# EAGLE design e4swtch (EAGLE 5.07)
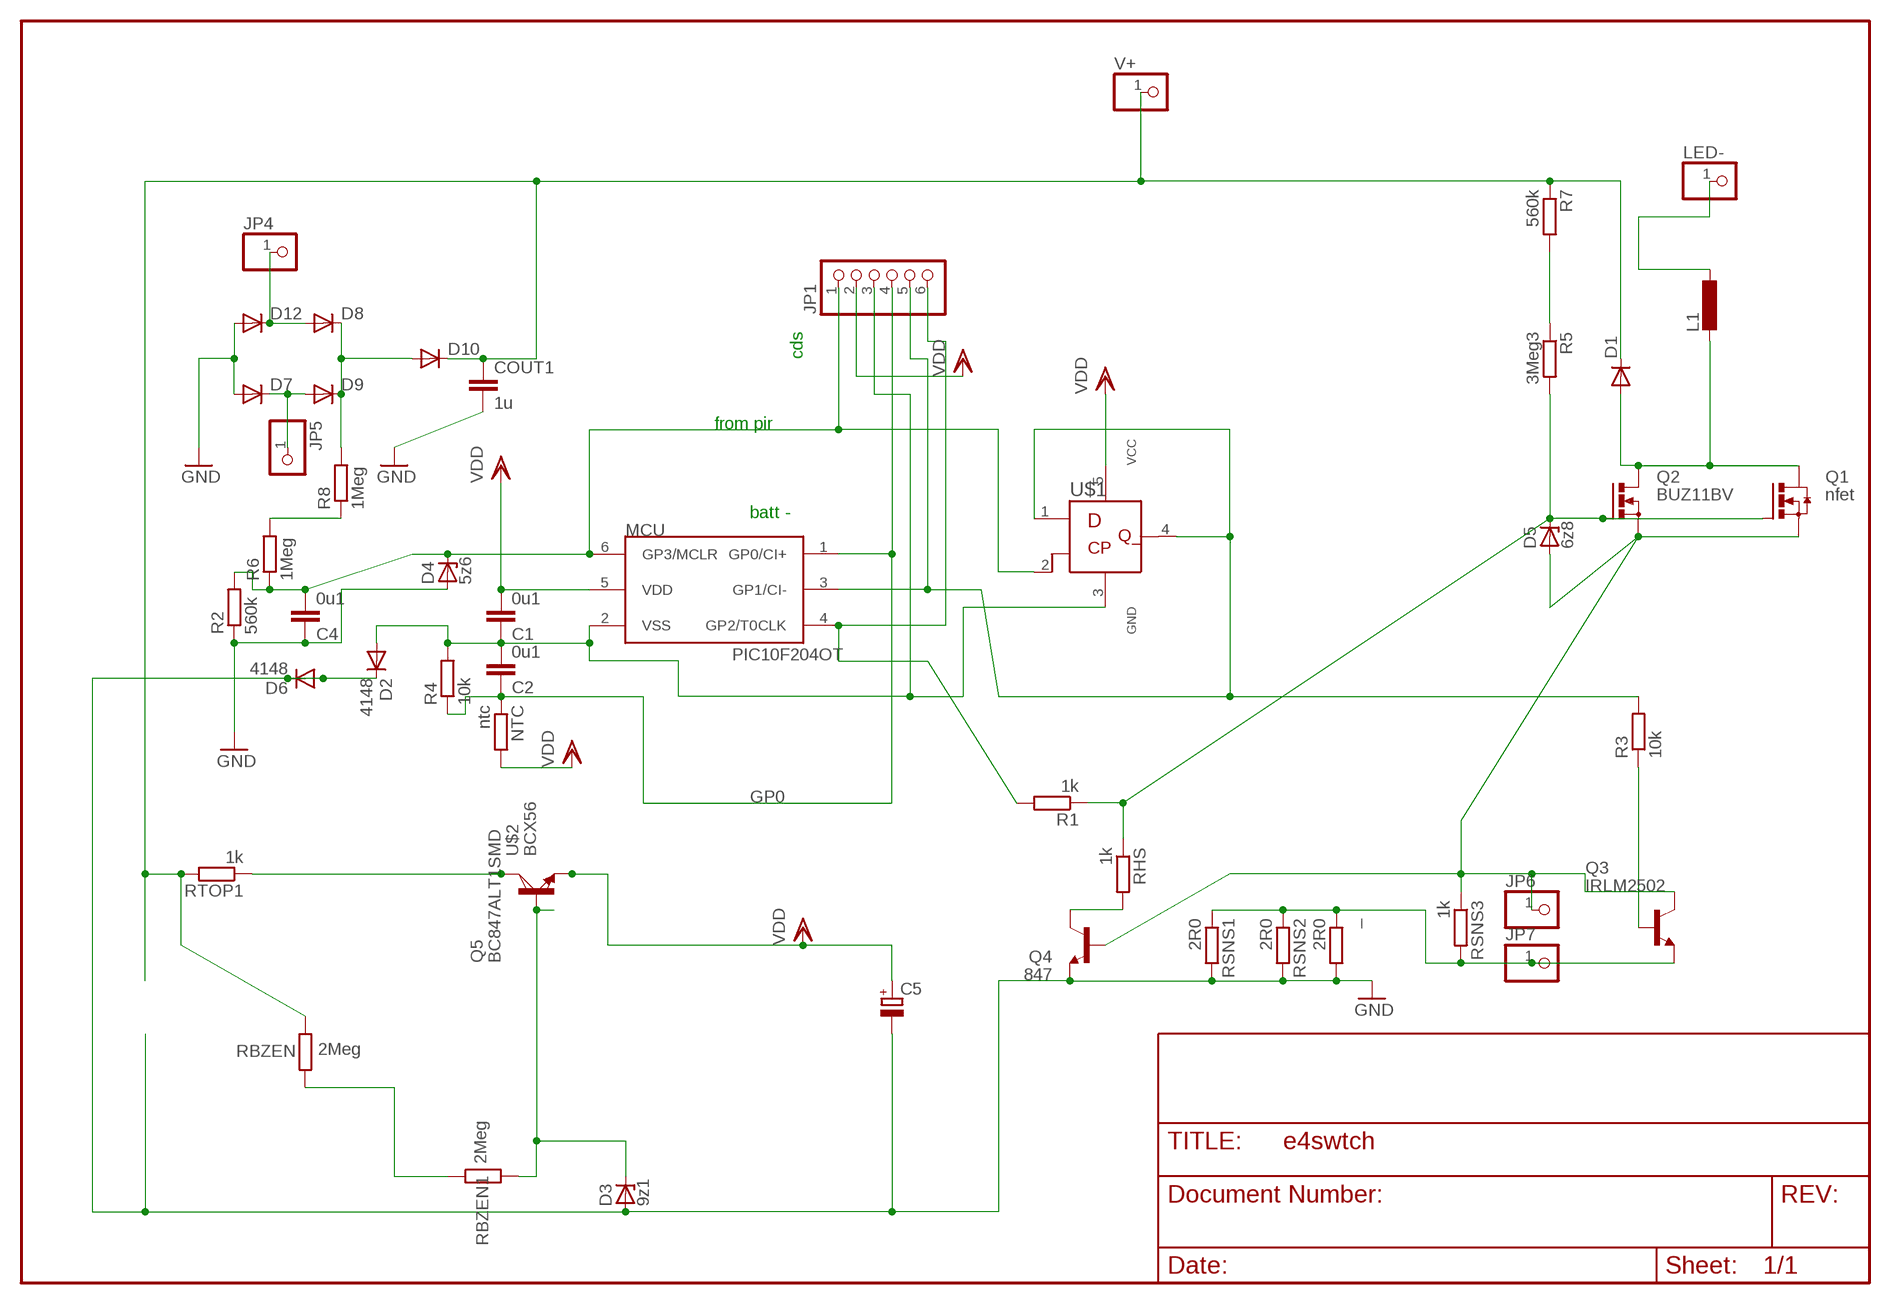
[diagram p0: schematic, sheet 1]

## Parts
_  2R0  R-EU_R2010  [R2010]
C1  0u1  C-EUC0805  [C0805]
C2  0u1  C-EUC0805  [C0805]
C4  0u1  C-EUC1206  [C1206]
C5  CPOL-EUSANYO_SMD_B6  [SANYO-OSCON_SMD_B6]
COUT1  1u  C-EU075-032X103  [C075-032X103]
D1  DIODE-SMC  [SMC]
D2  4148  1N4148MINIMELF  [MINIMELF]
D3  9z1  ZENER-DIODESOD80C  [SOD80C]
D4  5z6  ZENER-DIODESOD80C  [SOD80C]
D5  6z8  ZENER-DIODESOD80C  [SOD80C]
D6  4148  1N4148MINIMELF  [MINIMELF]
D7  DIODE-SMA-DO214  [SMA-DO214AC]
D8  DIODE-SMA-DO214  [SMA-DO214AC]
D9  DIODE-SMA-DO214  [SMA-DO214AC]
D10  DIODE-SMA-DO214  [SMA-DO214AC]
D12  DIODE-SMA-DO214  [SMA-DO214AC]
JP1  PINHD-1X6  [1X06BOX]
JP4  PINHD-1X11MM6  [1X1MM8]
JP5  PINHD-1X11MM6  [1X1MM8]
JP6  PINHD-1X1INCH  [1X01]
JP7  PINHD-1X1INCH  [1X01]
L1  L-EUPIS2816  [PIS2816]
LED-  PINHD-1X11MM6  [1X1MM8]
MCU  PIC10F204OT  [SOT23-6]
NTC  ntc  R-EU_0204/5  [0204/5]
Q1  nfet  N-HEXFET_DPAK-  [TO252]
Q2  BUZ11BV  [TO220BV]
Q3  IRLM2502  BC847ALT1SMD  [SOT23]
Q4  847  BC847ASMD  [SOT23]
Q5  BC847ALT1SMD  [SOT23]
R1  1k  R-EU_R0805  [R0805]
R2  560k  R-EU_R0805  [R0805]
R3  10k  R-EU_R0805  [R0805]
R4  10k  R-EU_R0805  [R0805]
R5  3Meg3  R-EU_R1206  [R1206]
R6  1Meg  R-EU_R1206  [R1206]
R7  560k  R-EU_R1206  [R1206]
R8  1Meg  R-EU_R1206  [R1206]
RBZEN  2Meg  R-EU_R1206  [R1206]
RBZEN1  2Meg  R-EU_R1206  [R1206]
RHS  1k  R-EU_0204/5  [0204/5]
RSNS1  2R0  R-EU_R2512  [R2512]
RSNS2  2R0  R-EU_R1206  [R1206]
RSNS3  1k  R-EU_R1206  [R1206]
RTOP1  1k  R-EU_R1206  [R1206]
U$1  7479SOT23  [SOT23-5]
U$2  BCX56  [SOT223]
V+  PINHD-1X11MM6  [1X1MM8]

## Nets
AC1: D8.A D12.K(C) JP4.1
AC2: D7.K(C) D9.A JP5.1
BSW1: _.1 JP7.1 Q3.2(E) RSNS1.1 RSNS2.1 RSNS3.2
C: Q5.3(C) RTOP1.1 U$2.2(C)
CB: D3.C Q5.1(B) RBZEN1.2 U$2.1(B)
GND: _.2 C4.1 C5.- COUT1.2 D2.C D3.A D4.A D6.A D6.C D7.A D12.A Q4.2(E) R2.1 RSNS1.2 RSNS2.2
GP0: C2.1 JP1.4 MCU.1(GP0/CI+) NTC.1 R4.1
HOT: D1.A L1.2 Q1.3(D) Q2.D
LED-: L1.1 LED-.1
N$1: D5.C Q1.1(G) Q2.G R1.1 R5.2 RHS.1
N$2: JP1.5 MCU.3(GP1/CI-) R3.2 U$1.1(D) U$1.4(Q_)
N$3: C4.2 D4.C JP1.1 MCU.6(GP3/MCLR) R2.2 R6.1 U$1.2(CP)
N$4: R5.1 R7.2
N$5: Q3.1(B) R3.1
N$6: RBZEN1.1 RBZEN.2
N$7: Q4.3(C) RHS.2
N$9: R6.2 R8.1
N$14: JP1.6 MCU.4(GP2/T0CLK) R1.2
N$16: D8.K(C) D9.K(C) D10.A R8.2
S: D5.A JP6.1 Q1.2(S) Q2.S Q3.3(C) Q4.1(B) RSNS3.1
VDD: C1.2 C5.+ JP1.2 MCU.5(VDD) NTC.2 Q5.2(E) U$1.5(VCC) U$2.3(E)
VPLUS: COUT1.1 D1.C D10.K(C) R7.1 RBZEN.1 RTOP1.2 V+.1
VSS: C1.1 C2.2 D2.A JP1.3 MCU.2(VSS) R4.2 U$1.3(GND)

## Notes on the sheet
- cds
- from pir
- batt -

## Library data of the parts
_ NTC R1 R3 R5 R7 RBZEN RBZEN1 RHS RSNS1-RSNS3 RTOP1 = rcl:R-EU_: RESISTOR, European symbol
C1 C2 C4 COUT1 = rcl:C-EU: CAPACITOR, European symbol
C5 = rcl-2:CPOL-EU: POLARIZED CAPACITOR, European symbol
D1 = diode-1:DIODE-: DIODE
D2 D6 = diode-1:1N4148: DIODE
D3-D5 = diode:ZENER-DIODE: Z-Diode
D7-D10 D12 = diode:DIODE-: DIODE
JP1 = pinhead:PINHD-1X6: PIN HEADER
JP4 JP5 LED- V+ = pinhead:PINHD-1X1: PIN HEADER
JP6 JP7 = pinhead(2):PINHD-1X1: PIN HEADER
L1 = rcl:L-EU: INDUCTOR, European symbol
MCU = microchip-3:PIC10F2*: uPC nW 0,25/0,5k Program Flash memory Comparator
Q1 = transistor-power:N-HEXFET_?-*: HEXFET® Power MOSFET
Q2 = transistor-power:BUZ11: N-CHANNEL MOS FET
Q3-Q5 = transistor-npn:BC847*: NPN Transistor
R2 R4 R6 R8 = rcl-2:R-EU_: RESISTOR, European symbol
U$1 = 74xx-little-de:7479
U$2 = transistor-power:BCX56

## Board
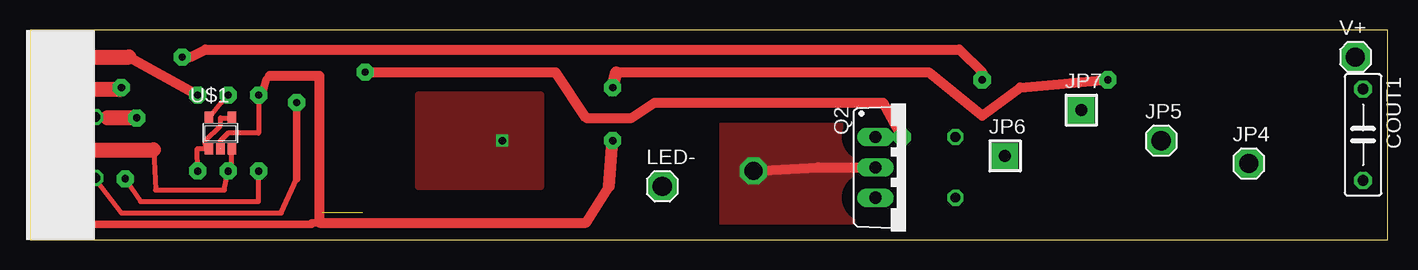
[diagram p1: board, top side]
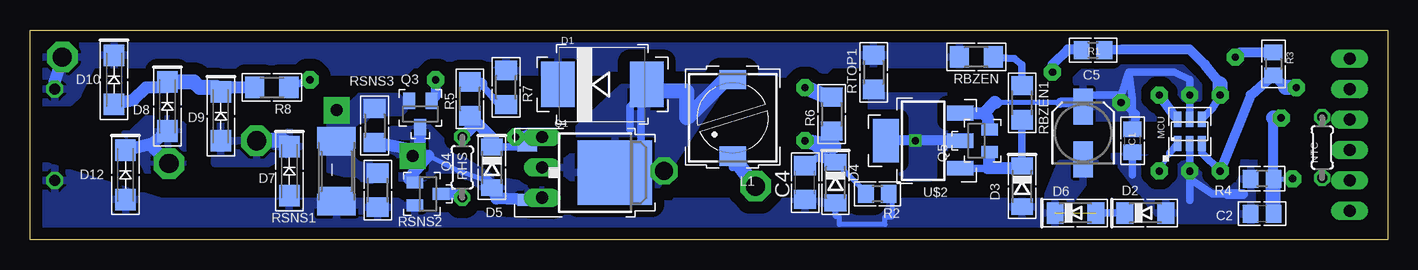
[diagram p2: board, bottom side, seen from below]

Size 113.19 x 17.5 mm. Coordinates in mm from the lower left corner, seen from the top.
Outline: 0,0 113.19,0 113.19,17.5 0,17.5 0,0
Copper layers (1*16): Top 0.035mm / dielectric 1.5mm / Bottom 0.035mm
Design rules "default *": minimum track width 10mil, minimum drill 24mil, track to track 8mil, track to pad 8mil, pad to pad 8mil, via to via 8mil, smd to smd 8mil, copper to edge 20mil, drill to drill 8mil, minimum pad ring 10mil, minimum via ring 8mil, stop-mask expansion 4mil, vias tented up to drill 0mil, thermal gap 10mil

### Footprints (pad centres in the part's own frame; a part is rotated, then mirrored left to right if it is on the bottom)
R2010 = smd 1.8 x 2.7: 1 -2.2,0; 2 2.2,0
C0805 = smd 1.3 x 1.5: 1 -0.95,0; 2 0.95,0
C1206 = smd 1.6 x 1.8: 1 -1.4,0; 2 1.4,0
SANYO-OSCON_SMD_B6 = smd 3 x 1.6: + 2.2,0; - -2.2,0
C075-032X103 = drill 0.914 octagon: 1 -3.81,0; 2 3.81,0
SMC = smd 2.8 x 3.8: A 3.7,0; C -3.7,0
MINIMELF = smd 1.4 x 1.8: A 1.7,0; C -1.7,0
SOD80C = smd 1.4 x 1.8: A 1.7,0; C -1.7,0
SMA-DO214AC = smd 1.8 x 1.7: A 2.05,-0.127; K -2.05,-0.127
1X06BOX = drill 1.016 long: 1 -6.35,0; 2 -3.81,0; 3 -1.27,0; 4 1.27,0; 5 3.81,0; 6 6.35,0
1X1MM8 = drill 1.6 pad 2.54 octagon: 1 0,0
1X01 = drill 1 pad 2.184 square: 1 0,0
PIS2816 = smd 2.2 x 1.6: 1 0,3.2; 2 0,-3.2
SOT23-6 = smd 0.635 x 1.27: 1 -1.016,-1.016; 2 0,-1.016; 3 1.016,-1.016; 4 1.016,1.016; 5 0,1.016; 6 -1.016,1.016
0204/5 = drill 0.813 octagon: 1 -2.54,0; 2 2.54,0
TO252 = smd 1 x 1.6: 1 -2.28,-3.53; 2 2.28,-3.53 | smd 5.4 x 6.2: 3 0,3.77
TO220BV = drill 1.016 long: D 0,-2.54; G -2.54,-2.54; S 2.54,-2.54
SOT23 = smd 1 x 1.4: 1 -0.95,-1.1; 2 0.95,-1.1; 3 0,1.1
R0805 = smd 1.3 x 1.5: 1 -0.95,0; 2 0.95,0
R1206 = smd 1.6 x 1.803: 1 -1.422,0; 2 1.422,0
R2512 = smd 1.8 x 3.2: 1 -2.8,0; 2 2.8,0
SOT23-5 = smd 0.69 x 0.99: 1 -0.95,-1.29; 2 0,-1.29; 3 0.95,-1.29; 4 0.95,1.3; 5 -0.95,1.3
SOT223 = smd 1.219 x 2.235: 1 -2.311,-3.099; 2 0,-3.099; 3 2.311,-3.099 | smd 3.6 x 2.2: 4 0,3.099

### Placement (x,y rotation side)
_  87.63,5.71 270 bottom
C1  21.27,8.26 90 bottom
C2  10.48,2.16 180 bottom
C4  48.58,4.76 90 bottom
C5  25.4,8.89 90 bottom
COUT1  111.12,8.75 270 top
D1  65.47,12.95 0 bottom
D2  20.2,2.22 0 bottom
D3  30.48,4.45 270 bottom
D4  46.04,4.76 270 bottom
D5  74.68,6.03 270 bottom
D6  26.04,2.22 0 bottom
D7  91.44,5.71 270 bottom
D8  101.6,11.11 270 bottom
D9  97.16,10.29 270 bottom
D10  106.05,13.34 270 bottom
D12  105.09,5.4 270 bottom
JP1  3.17,8.75 90 top
JP4  101.6,6.35 0 top
JP5  94.3,8.26 0 top
JP6  81.28,6.99 0 top
JP7  87.63,10.79 0 top
L1  54.61,10.16 180 bottom
LED-  52.7,4.45 0 top
MCU  16.51,9.03 0 bottom
NTC  5.46,7.68 270 bottom
Q1  68.2,5.59 270 bottom
Q2  73.03,6.03 270 top
Q3  80.64,10.48 180 bottom
Q4  80.01,3.81 270 bottom
Q5  34.29,8.26 90 bottom
R1  24.57,15.81 0 bottom
R2  42.55,3.81 180 bottom
R3  9.53,14.67 270 bottom
R4  10.48,5.08 180 bottom
R5  76.52,11.75 270 bottom
R6  46.35,10.48 90 bottom
R7  73.5,12.7 270 bottom
R8  93.03,12.7 180 bottom
RBZEN  34.29,15.24 0 bottom
RBZEN1  30.48,11.43 270 bottom
RHS  77.15,6.03 270 bottom
RSNS1  87.63,5.71 270 bottom
RSNS2  84.2,4.13 270 bottom
RSNS3  84.45,9.53 90 bottom
RTOP1  42.86,13.97 90 bottom
U$1  15.88,8.89 0 top
U$2  38.73,8.26 90 bottom
V+  110.49,15.24 0 top

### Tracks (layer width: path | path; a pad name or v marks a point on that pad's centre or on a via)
AC1
  Bottom 1.016: 103.2,7.95 D12.K | JP4.1 103.2,7.95 | 103.2,7.95 103.06,7.95 D8.A
  pour Bottom (isolate 0.813, rank 2): 100.97,10.16 103.5,10.16 104.78,8.89 105.41,8.89 104.78,8.26 103.5,5.71 100.33,5.71 100.33,9.53
AC2
  Bottom 1.27: JP5.1 92.06,8.26 D7.K
  pour Bottom (isolate 0.813): 97.79,9.53 90.81,8.89 90.81,7.62 93.34,6.35 97.79,6.35
BSW1
  pour Bottom (isolate 0.813, rank 2, no thermals): 88.27,5.71 88.27,10.79 87.63,11.43 86.36,11.43 85.72,12.06 82.55,12.06 81.92,11.43 81.92,10.79 82.23,10.48 84.77,10.48 85.72,9.53 86.04,7.62 84.77,6.35 84.77,4.76
C  (via drill 0.6)
  Bottom 0.813: 41.91,8.26 v39.37,8.26 Q5.3
  Bottom 1.016: Q5.3 U$2.2
  pour Top (isolate 0.61, rank 4): 32.38,12.06 42.55,12.06 42.55,4.45 32.38,4.45
  pour Bottom (isolate 0.813, no thermals): 36.83,12.06 43.18,12.06 43.18,5.08 38.1,5.08 36.83,5.71
CB
  Bottom 0.61: RBZEN1.2 D3.C 30.65,5.97 | 33.33,5.94 U$2.1
  Bottom 1.016: 33.02,5.94 30.68,5.94 D3.C | 33.02,5.94 33.33,5.94 | Q5.1 33.19,6.11 33.02,5.94
GND  (1 unrouted)
  Bottom 0.406: R2.1 41.27,3.81 41.27,1.91 41.91,1.91 41.91,1.27 45.72,1.27 45.72,1.91 46.04,1.91 D4.A
  Bottom 0.61: D2.C D6.A
  pour Bottom (isolate 1.016, rank 4): 28.57,3.17 102.23,3.17 112.39,6.35 112.39,0.64 26.99,0.64 26.99,2.54 24.13,6.35 27.3,6.35
GP0  (via drill 0.6 pad 1.42)
  Top 0.406: v19.05,5.71 19.05,3.17 9.21,3.17 v7.94,5.08
  Top 0.61: 3.31,10.16 JP1.4
  Top 0.813: 5.14,10.16 5.08,10.16 | 6.48,10.16 NTC.1
  Top 1.27: 5.08,10.16 3.31,10.16 | NTC.1 5.14,10.16 | v8.89,10.16 6.48,10.16
  Bottom 0.406: R4.1 v7.94,5.08 | v19.05,5.71 18.16,7.24
  Bottom 0.61: 18.16,7.24 MCU.1
  Bottom 0.813: R4.1 9.53,10.16
  Bottom 1.27: 9.53,10.16 v8.89,10.16 | C2.1 R4.1
HOT  (via drill 1.5 pad 1.42)
  Top 0.813: Q2.D 65.72,6.03 v60.33,5.71
  Bottom 0.61: 62.23,11.43 62.23,6.35 64.43,6.35 Q1.3 | 62.23,11.43 62.23,12.13 62.05,12.46 D1.A 60.5,12.72 | 63.18,9.21 63.18,11.11 62.87,11.43 62.23,11.43
  Bottom 1.27: L1.2 55.22,13.36 58.42,10.16 58.42,12.38 61.97,12.38 62.05,12.46
  pour Bottom (isolate 1.27): 55.56,12.7 63.82,12.7 68.58,8.26 69.22,8.26 69.22,3.49 61.59,3.49
  pour Top (isolate 1.27): 57.78,10.79 66.67,10.79 68.58,8.26 68.58,1.27 57.78,1.27
LED-
  Bottom 0.61: L1.1 54.61,6.03
  Bottom 1.27: LED-.1 52.73,4.45 L1.1
N$1  (via drill 0.6 pad 1.42)
  Top 0.813: v72.71,8.57 71.12,11.43 52.07,11.43 50.16,10.16 46.35,10.16 43.81,13.97 v27.94,13.97
  Bottom 0.406: D5.C 74.61,8.42 | R5.2 76.2,9.53
  Bottom 0.61: D5.C 71.99,7.73 Q1.1 71.73,8.87 v72.71,8.57 Q2.G | R1.1 25.59,15.88
  Bottom 0.813: v27.94,13.97 27.94,14.61 26.67,15.88 25.59,15.88
  Bottom 1.016: 74.61,8.42 R5.2 | 76.2,9.53 RHS.1
N$2  (via drill 0.6 pad 1.42)
  Top 0.406: 7.48,12.56 v7.62,12.7 | v13.97,5.71 13.95,7.6 U$1.1 14.61,7.92 14.61,8.26 15.88,9.53 15.88,10.16 16.8,10.16 U$1.4
  Top 1.27: JP1.5 7.48,12.56
  Bottom 0.406: 15.49,7.24 MCU.3
  Bottom 0.61: v13.97,5.71 15.49,7.24
  Bottom 0.813: 8.51,12.7 R3.2 11.43,12.06 v13.97,5.71
  Bottom 1.27: v7.62,12.7 8.51,12.7
N$3  (via drill 0.6 pad 1.42)
  Top 0.406: U$1.2 15.88,8.26 16.51,8.89 19.05,8.89 19.05,12.14 19.5,12.59
  Top 0.61: 4.13,1.27 23.5,1.27 23.5,1.4 24.13,1.4 | 20,13.65 19.68,13.34 19.5,12.59 19.37,12.06 v19.05,12.06
  Top 0.813: 20,13.65 24.13,13.65 24.13,1.4 46.35,1.4 48.26,4.45
  Top 1.016: 48.26,4.45 v48.58,8.26
  Top 1.27: JP1.1 4.13,1.27
  Bottom 0.406: R2.2 43.49,3.92 D4.C
  Bottom 0.61: 17.78,10.3 MCU.6 | C4.2 47.61,6.8 D4.C 47.1,7.1 v48.58,8.26 | 46.19,7.79 R6.1
  Bottom 0.813: v19.05,12.06 17.78,10.3
  Bottom 1.27: v48.58,8.26 46.19,7.79
N$4
  Bottom 0.406: R7.2 74.14,11.28 | 76.05,13.02 R5.1
  Bottom 0.61: 74.14,11.28 75.56,13.02
  Bottom 1.016: 75.56,13.02 76.05,13.02
N$5  (via drill 0.6 pad 1.42)
  Top 0.813: v12.7,15.24 13.34,15.24 14.61,15.88 77.47,15.88 79.38,13.97 v79.38,13.34
  Bottom 0.406: 79.38,11.9 Q3.1
  Bottom 0.813: R3.1 12.32,15.62 v12.7,15.24 | v79.38,13.34 79.38,11.9
N$6
  Bottom 0.61: RBZEN1.1 30.48,14.61 31.11,15.09 RBZEN.2
N$7
  Bottom 0.406: RHS.2 77.62,3.81
  Bottom 1.016: 77.62,3.81 Q4.3
N$9  (via drill 0.6 pad 1.42)
  Top 0.813: 48.9,13.97 74.93,13.97 79.38,10.34 82.55,12.7 v89.85,13.34
  Top 1.016: v48.58,12.7 48.9,13.97
  Bottom 0.61: R6.2 47.14,12.06 | v89.85,13.34 R8.1
  Bottom 1.27: 47.14,12.06 v48.58,12.7
N$14  (via drill 0.6 pad 1.42)
  Top 0.813: 8.26,15.24 v13.97,12.06 | JP1.6 3.31,15.24
  Top 1.27: 3.31,15.24 8.26,15.24
  Bottom 0.61: v13.97,12.06 14.61,10.94 MCU.4
  Bottom 0.813: R1.2 22.16,15.88 16.51,15.88 15.24,14.61 13.97,13.02
  Bottom 1.27: v13.97,12.06 13.97,13.02
N$16
  Bottom 1.016: D10.A 104.57,11.63 103.5,12.7 101.71,12.7 D8.K | D9.K 97.16,12.06 96.52,12.7 R8.2
  Bottom 1.27: D8.K 99.52,13.16 99.06,12.7 97.64,12.7 D9.K
S
  Bottom 0.406: D5.A 74.61,4.76 74.93,5.08 75.56,5.08 77.47,5.71 80,7.01 80.64,7.45 | 81.61,5.08 Q4.1
  Bottom 0.61: Q2.S 71.73,3.49 Q1.2 | 74.3,3.42 74.3,3.81 74.61,3.81 D5.A
  Bottom 1.016: Q1.2 74.3,3.42 | 80.64,7.45 Q3.3 | 80,7.01 81.61,5.08 | RSNS3.1 81.92,7.62 JP6.1
  pour Bottom (isolate 0.813, rank 3): 70.48,4.45 74.3,5.08 77.47,6.99 80.01,9.53 83.82,9.53 83.82,6.35 82.55,5.08 80.01,5.08 79.38,5.71 77.47,5.71 75.56,3.81 70.48,3.17
VDD  (via drill 0.6 pad 1.42)
  Top 0.406: 5.54,4.94 7.62,2.22 20.95,2.22 22.23,5.08 | U$1.5 15.9,11.4 v16.51,12.06
  Top 0.61: JP1.2 5.54,4.94 | 22.23,5.08 v22.23,11.43
  Top 0.813: JP1.2 3.38,5.14
  Top 1.27: 3.38,5.14 NTC.2
  Bottom 0.406: 27.3,11.43 32.65,11.43
  Bottom 0.61: 34.34,10.54 U$2.3 | 26.04,11.43 C5.+ 25.4,12.06 22.23,12.06 21.59,13.97 | MCU.5 v16.51,12.06 16.51,13.34 17.78,13.97 21.59,13.97 | 21.59,13.97 21.27,11.75 21.27,10.48 20.95,10.16 C1.2 20.96,10.48 v22.23,11.43
  Bottom 0.813: 26.04,11.43 27.3,11.43
  Bottom 1.016: 33.72,10.54 34.34,10.54 | 33.72,10.54 33.34,10.16 33.34,9.35 Q5.2 | 32.65,11.43 32.77,11.49 33.72,10.54
  pour Bottom (isolate 0.813, rank 2): 24.77,10.16 13.34,10.16 13.34,13.97 13.97,14.61 24.77,14.61 26.04,13.34
VPLUS
  Bottom 1.016: V+.1 111.12,13.2 COUT1.1
  pour Bottom (isolate 1.016, rank 3): 112.71,15.88 112.39,13.65 112.39,11.43 109.86,11.43 109.22,12.06 107.95,14.61 103.5,14.61 102.87,13.97 81.92,13.97 81.28,14.61 74.3,14.61 73.66,13.97 50.8,13.97 48.9,12.7 48.26,12.7 46.35,14.61 35.56,14.61 35.56,16.51 111.12,16.51
VSS  (via drill 0.6 pad 1.42)
  Top 0.406: 10.3,7.48 10.48,4.13 16.19,4.13 v16.51,5.71 16.82,6.03 U$1.3
  Top 1.27: JP1.3 10.3,7.48
  Bottom 0.61: C1.1 21.27,5.4 | 16.51,5.08 v16.51,5.71 MCU.2 | 16.51,5.08 16.51,3.27 | 16.51,5.08 14.61,3.81 13.34,3.81
  Bottom 0.813: 13.34,3.81 12.06,3.81
  pour Bottom (isolate 0.813): 10.79,6.35 22.86,6.99 18.73,1.59 10.48,1.59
